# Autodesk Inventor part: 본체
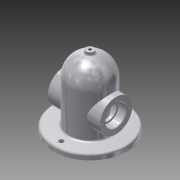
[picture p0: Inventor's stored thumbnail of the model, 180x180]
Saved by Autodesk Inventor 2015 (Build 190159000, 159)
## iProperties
Created: 2019-11
Part Number: 본체
Material: 알루미늄 6061
Document SubType Name: Modeling
Designer: now
Density: 2.7 g/cm^3
Appearance: 알루미늄 - 평지
Mass: 1105.31 g
Surface Area: 885.477 cm^2
Volume: 409.375 cm^3
Author: now
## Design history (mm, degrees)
sketch "스케치1"
  geometry: C1 r 70 at (0, 0); 1 further point
  constraints: 1 centre point, 1 coincident
  dimensions: "d0" = 140 diameter of C1
extrude "돌출1" new body sketch "스케치1" distance "d1" = 10; taper "d2" = 0 deg
sketch "스케치2"
  geometry: C1 r 70 at (0, 0) reference; C2 r 40 at (0, 0)
  constraints: 1 centre point, 1 coincident
  dimensions: "d3" = 80 diameter of C2
extrude "돌출2" join sketch "스케치2" distance "d4" = 120; taper "d5" = 0 deg
fillet "모깎기1" dims "d6" = 40
node "작업 평면1"
feature "쉘1" dims "d12" = 10
node "작업 평면2"
sketch "스케치4"
  geometry: L1 (-70, 0)-(70, 0) reference; C1 r 31 at (0, 50); 2 further points
  constraints: 1 centre point, 1 coincident, 1 vertical alignment
  dimensions: "d14" = 50 distance from line of L1 point (0, 50); "d15" = 62 diameter of C1
extrude "돌출4" join sketch "스케치4" distance "d16" = 100; taper "d17" = 0 deg
node "작업 평면3"
sketch "스케치5"
  geometry: C1 r 7.5 at (0, 0); 1 further point
  constraints: 1 centre point, 1 coincident
  dimensions: "d19" = 15 diameter of C1
extrude "돌출5" join sketch "스케치5" stored distance "d20" = 15 (= d19); taper "d21" = 0 deg
sketch "스케치6"
  geometry: C1 r 31 at (0, 0) reference; C2 r 16.5 at (0, 0); 1 further point
  constraints: 1 centre point, 1 coincident
  dimensions: "d22" = 33 diameter of C2
extrude "돌출6" cut sketch "스케치6" stored distance "d23" = 100; taper "d24" = 0 deg
sketch "스케치7"
  geometry: C1 r 16.5 at (0, 0) reference; C2 r 31 at (0, 0) reference; C3 r 20 at (0, 0); 1 further point
  constraints: 1 centre point, 1 coincident
  dimensions: "d25" = 40 diameter of C3
extrude "돌출7" cut sketch "스케치7" distance "d26" = 15; taper "d27" = 0 deg
sketch "스케치8"
  geometry: C1 r 16.5 at (0, 0) reference; C2 r 31 at (0, 0) reference; C3 r 20 at (0, 0); 1 further point
  constraints: 1 centre point, 1 coincident
  dimensions: "d28" = 40 diameter of C3
extrude "돌출8" cut sketch "스케치8" distance "d29" = 15; taper "d30" = 0 deg
sketch "스케치9"
  geometry: C1 r 7.5 at (0, 0) reference
hole "구멍1" sketch "스케치9" at (0, 0) diameter "d31" = 5.188; stored, may be unused: countersink angle "d35" = 90 deg, drill point angle "d37" = 118 deg; dims "d32" = 12, "d33" = 4, "d34" = 2, "d36" = 30
sketch "스케치10"
  geometry: C1 r 30 at (0, 0) reference; C2 r 70 at (0, 0) reference; C3 r 30 at (0, 0)
  constraints: 1 centre point, 1 coincident
  dimensions: "d38" = 60 diameter of C3
extrude "돌출9" cut sketch "스케치10" stored distance "d39" = 15; taper "d40" = 0 deg
sketch "스케치11"
  geometry: C1 r 20 at (0, 0) reference; 2 further points
  constraints: 1 horizontal alignment
  dimensions: "d41" = 26 distance of C1.centre point (-26, 0)
hole "구멍2" sketch "스케치11" at (-26, 0) diameter "d42" = 3.242; stored, may be unused: countersink angle "d46" = 90 deg, drill point angle "d48" = 118 deg; dims "d43" = 8, "d44" = 4, "d45" = 2, "d47" = 10
node "작업 평면4"
sketch "스케치12"
  geometry: L1 (-70, 0)-(70, 0) reference; 2 further points
  constraints: 1 vertical alignment, 1 other
  dimensions: "d53" = 50 distance from line of L1 point (0, 50)
feature "엠보싱1" sketch "스케치12" dims "d54" = 0.5, "d55" = 0
sketch "스케치13" dims "d56" = 110
  geometry: C1 r 70 at (0, 0) reference; C2 r 4.5 at (0, -55); 1 further point
  constraints: 1 centre point, 1 coincident, 1 vertical alignment, 2 other
  dimensions: "d57" = 9 diameter of C2
extrude "돌출10" cut sketch "스케치13" stored distance "d58" = 15; taper "d59" = 0 deg
fillet "모깎기2" dims "d60" = 3
chamfer "모따기1" distance "d61" = 1; stored, may be unused: second distance "d62" = 2, angle "d63" = 45 deg
fillet "모깎기3" dims "d64" = 0.3
node "솔리드1"
pattern_circular "원형 패턴1" dims angle "d50" = 360 deg
mirror "대칭1"
mirror "대칭2"
other parameters: "d18" = 135
